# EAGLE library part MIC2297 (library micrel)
40V PWM Boost Regulator White LED Driver Source: http://www.micrel.com/_PDF/mic2297.pdf
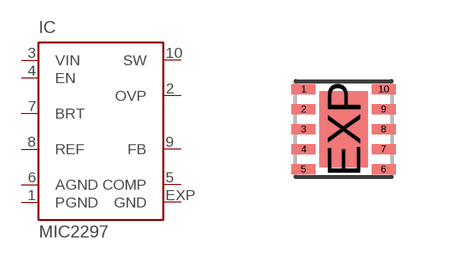
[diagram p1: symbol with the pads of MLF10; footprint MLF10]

Designator prefix IC

## MIC2297 (MPN: MIC2297-38YML TR; OC_FARNELL: 1663107; OC_NEWARK: 11R3489)  [MLF10]
1  PGND  in
2  OVP  in
3  VIN  in
4  EN  in
5  COMP  pas
6  AGND  in
7  BRT  in
8  REF  in
9  FB  in
10  SW  oc
EXP  GND  in

## Footprint MLF10 (pad centres in mm)
MLF 10 (ML) 2.5 x 2.5 mm, 10-Pin Package Source: Source: http://www.micrel.com/_PDF/mic2297.pdf
smd 0.6 x 0.25: 1 -1,1; 2 -1,0.5; 3 -1,0; 4 -1,-0.5; 5 -1,-1; 6 1,-1; 7 1,-0.5; 8 1,0; 9 1,0.5; 10 1,1
smd 1.2 x 1.9: EXP 0,0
